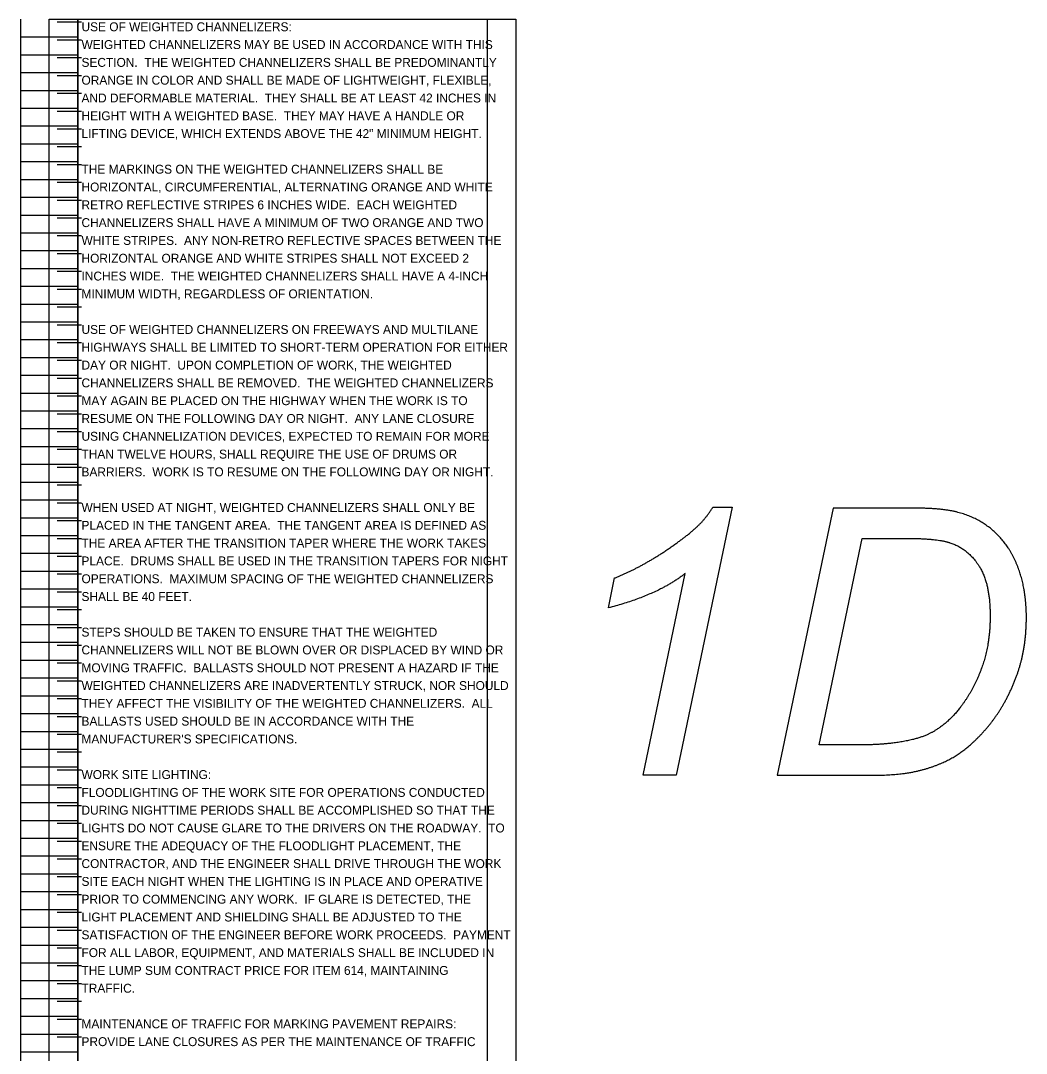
# Model space of a CAD drawing. Extents: x 12522 to 13018, y 1124 to 1902.
# Drawn here: x 12563.34 to 12579.16, y 1773.05 to 1789.29 of the extents above; entities that cross this region are included whole.
import ezdxf

# ---------------------------------------------------------------- set-up
doc = ezdxf.new("R2010")
doc.units = 0
doc.layers.add('SC_Scratch1', color=7, linetype='Continuous')
doc.layers.add('SH_Text', color=7, linetype='Continuous')

msp = doc.modelspace()

# ---------------------------------------------------------------- linework, layer by layer
at = {"layer": 'SC_Scratch1'}
for p, q in [((12563.336, 1769.151), (12563.336, 1789.311)), ((12563.336, 1769.151), (12563.336, 1789.311)), ((12564.293, 1789.261), (12563.909, 1789.261)), ((12564.236, 1769.151), (12564.236, 1789.311)), ((12564.236, 1789.311), (12564.236, 1769.151)), ((12564.236, 1769.151), (12564.236, 1789.311)), ((12563.336, 1789.031), (12564.236, 1789.031)), ((12563.336, 1789.031), (12564.236, 1789.031)), ((12564.293, 1788.981), (12563.909, 1788.981)), ((12563.336, 1788.751), (12564.236, 1788.751)), ((12563.336, 1788.751), (12564.236, 1788.751)), ((12564.293, 1788.701), (12563.909, 1788.701)), ((12563.336, 1788.471), (12564.236, 1788.471)), ((12563.336, 1788.471), (12564.236, 1788.471)), ((12564.293, 1788.421), (12563.909, 1788.421)), ((12563.336, 1788.191), (12564.236, 1788.191)), ((12563.336, 1788.191), (12564.236, 1788.191)), ((12564.293, 1788.141), (12563.909, 1788.141)), ((12563.336, 1787.911), (12564.236, 1787.911)), ((12563.336, 1787.911), (12564.236, 1787.911)), ((12564.293, 1787.861), (12563.909, 1787.861)), ((12563.336, 1787.631), (12564.236, 1787.631)), ((12563.336, 1787.631), (12564.236, 1787.631)), ((12564.293, 1787.581), (12563.909, 1787.581)), ((12563.336, 1787.351), (12564.236, 1787.351)), ((12563.336, 1787.351), (12564.236, 1787.351)), ((12564.293, 1787.301), (12563.909, 1787.301)), ((12563.336, 1787.071), (12564.236, 1787.071)), ((12563.336, 1787.071), (12564.236, 1787.071)), ((12564.293, 1787.021), (12563.909, 1787.021)), ((12563.336, 1786.791), (12564.236, 1786.791)), ((12563.336, 1786.791), (12564.236, 1786.791)), ((12564.293, 1786.741), (12563.909, 1786.741)), ((12563.336, 1786.511), (12564.236, 1786.511)), ((12563.336, 1786.511), (12564.236, 1786.511)), ((12564.293, 1786.461), (12563.909, 1786.461)), ((12563.336, 1786.231), (12564.236, 1786.231)), ((12563.336, 1786.231), (12564.236, 1786.231)), ((12564.293, 1786.181), (12563.909, 1786.181)), ((12563.336, 1785.951), (12564.236, 1785.951)), ((12563.336, 1785.951), (12564.236, 1785.951)), ((12564.293, 1785.901), (12563.909, 1785.901)), ((12563.336, 1785.671), (12564.236, 1785.671)), ((12563.336, 1785.671), (12564.236, 1785.671)), ((12564.293, 1785.621), (12563.909, 1785.621)), ((12563.336, 1785.391), (12564.236, 1785.391)), ((12563.336, 1785.391), (12564.236, 1785.391)), ((12564.293, 1785.341), (12563.909, 1785.341)), ((12563.336, 1785.111), (12564.236, 1785.111)), ((12563.336, 1785.111), (12564.236, 1785.111)), ((12564.293, 1785.061), (12563.909, 1785.061)), ((12563.336, 1784.831), (12564.236, 1784.831)), ((12563.336, 1784.831), (12564.236, 1784.831)), ((12564.293, 1784.781), (12563.909, 1784.781)), ((12563.336, 1784.551), (12564.236, 1784.551)), ((12563.336, 1784.551), (12564.236, 1784.551)), ((12564.293, 1784.501), (12563.909, 1784.501)), ((12563.336, 1784.271), (12564.236, 1784.271)), ((12563.336, 1784.271), (12564.236, 1784.271)), ((12564.293, 1784.221), (12563.909, 1784.221)), ((12563.336, 1783.991), (12564.236, 1783.991)), ((12563.336, 1783.991), (12564.236, 1783.991)), ((12564.293, 1783.941), (12563.909, 1783.941)), ((12563.336, 1783.711), (12564.236, 1783.711)), ((12563.336, 1783.711), (12564.236, 1783.711)), ((12564.293, 1783.661), (12563.909, 1783.661)), ((12563.336, 1783.431), (12564.236, 1783.431)), ((12563.336, 1783.431), (12564.236, 1783.431)), ((12564.293, 1783.381), (12563.909, 1783.381)), ((12563.336, 1783.151), (12564.236, 1783.151)), ((12563.336, 1783.151), (12564.236, 1783.151)), ((12564.293, 1783.101), (12563.909, 1783.101)), ((12563.336, 1782.871), (12564.236, 1782.871)), ((12563.336, 1782.871), (12564.236, 1782.871)), ((12564.293, 1782.821), (12563.909, 1782.821)), ((12563.336, 1782.591), (12564.236, 1782.591)), ((12563.336, 1782.591), (12564.236, 1782.591)), ((12564.293, 1782.541), (12563.909, 1782.541)), ((12563.336, 1782.311), (12564.236, 1782.311)), ((12563.336, 1782.311), (12564.236, 1782.311)), ((12564.293, 1782.261), (12563.909, 1782.261)), ((12563.336, 1782.031), (12564.236, 1782.031)), ((12563.336, 1782.031), (12564.236, 1782.031)), ((12564.293, 1781.981), (12563.909, 1781.981)), ((12563.336, 1781.751), (12564.236, 1781.751)), ((12563.336, 1781.751), (12564.236, 1781.751)), ((12564.293, 1781.701), (12563.909, 1781.701)), ((12563.336, 1781.471), (12564.236, 1781.471)), ((12563.336, 1781.471), (12564.236, 1781.471)), ((12564.293, 1781.421), (12563.909, 1781.421)), ((12563.336, 1781.191), (12564.236, 1781.191)), ((12563.336, 1781.191), (12564.236, 1781.191)), ((12564.293, 1781.141), (12563.909, 1781.141)), ((12563.336, 1780.911), (12564.236, 1780.911)), ((12563.336, 1780.911), (12564.236, 1780.911)), ((12564.293, 1780.861), (12563.909, 1780.861)), ((12563.336, 1780.631), (12564.236, 1780.631)), ((12563.336, 1780.631), (12564.236, 1780.631)), ((12564.293, 1780.581), (12563.909, 1780.581)), ((12572.582, 1780.052), (12572.68, 1780.523)), ((12572.582, 1780.052), (12572.68, 1780.523)), ((12563.336, 1780.351), (12564.236, 1780.351)), ((12563.336, 1780.351), (12564.236, 1780.351)), ((12564.293, 1780.301), (12563.909, 1780.301)), ((12563.336, 1780.071), (12564.236, 1780.071)), ((12563.336, 1780.071), (12564.236, 1780.071)), ((12564.293, 1780.021), (12563.909, 1780.021)), ((12563.336, 1779.791), (12564.236, 1779.791)), ((12563.336, 1779.791), (12564.236, 1779.791)), ((12564.293, 1779.741), (12563.909, 1779.741)), ((12563.336, 1779.511), (12564.236, 1779.511)), ((12563.336, 1779.511), (12564.236, 1779.511)), ((12564.293, 1779.461), (12563.909, 1779.461)), ((12563.336, 1779.231), (12564.236, 1779.231)), ((12563.336, 1779.231), (12564.236, 1779.231)), ((12564.293, 1779.181), (12563.909, 1779.181)), ((12563.336, 1778.951), (12564.236, 1778.951)), ((12563.336, 1778.951), (12564.236, 1778.951)), ((12564.293, 1778.901), (12563.909, 1778.901)), ((12563.336, 1778.671), (12564.236, 1778.671)), ((12563.336, 1778.671), (12564.236, 1778.671)), ((12564.293, 1778.621), (12563.909, 1778.621)), ((12563.336, 1778.391), (12564.236, 1778.391)), ((12563.336, 1778.391), (12564.236, 1778.391)), ((12564.293, 1778.341), (12563.909, 1778.341)), ((12563.336, 1778.111), (12564.236, 1778.111)), ((12563.336, 1778.111), (12564.236, 1778.111)), ((12564.293, 1778.061), (12563.909, 1778.061)), ((12563.336, 1777.831), (12564.236, 1777.831)), ((12563.336, 1777.831), (12564.236, 1777.831)), ((12564.293, 1777.781), (12563.909, 1777.781)), ((12563.336, 1777.551), (12564.236, 1777.551)), ((12563.336, 1777.551), (12564.236, 1777.551)), ((12564.293, 1777.501), (12563.909, 1777.501)), ((12563.336, 1777.271), (12564.236, 1777.271)), ((12563.336, 1777.271), (12564.236, 1777.271)), ((12564.293, 1777.221), (12563.909, 1777.221)), ((12563.336, 1776.991), (12564.236, 1776.991)), ((12563.336, 1776.991), (12564.236, 1776.991)), ((12564.293, 1776.941), (12563.909, 1776.941)), ((12563.336, 1776.711), (12564.236, 1776.711)), ((12563.336, 1776.711), (12564.236, 1776.711)), ((12564.293, 1776.661), (12563.909, 1776.661)), ((12563.336, 1776.431), (12564.236, 1776.431)), ((12563.336, 1776.431), (12564.236, 1776.431)), ((12564.293, 1776.381), (12563.909, 1776.381)), ((12563.336, 1776.151), (12564.236, 1776.151)), ((12563.336, 1776.151), (12564.236, 1776.151)), ((12564.293, 1776.101), (12563.909, 1776.101)), ((12563.336, 1775.871), (12564.236, 1775.871)), ((12563.336, 1775.871), (12564.236, 1775.871)), ((12564.293, 1775.821), (12563.909, 1775.821)), ((12563.336, 1775.591), (12564.236, 1775.591)), ((12563.336, 1775.591), (12564.236, 1775.591)), ((12564.293, 1775.541), (12563.909, 1775.541)), ((12563.336, 1775.311), (12564.236, 1775.311)), ((12563.336, 1775.311), (12564.236, 1775.311)), ((12564.293, 1775.261), (12563.909, 1775.261)), ((12563.336, 1775.031), (12564.236, 1775.031)), ((12563.336, 1775.031), (12564.236, 1775.031)), ((12564.293, 1774.981), (12563.909, 1774.981)), ((12563.336, 1774.751), (12564.236, 1774.751)), ((12563.336, 1774.751), (12564.236, 1774.751)), ((12564.293, 1774.701), (12563.909, 1774.701)), ((12563.336, 1774.471), (12564.236, 1774.471)), ((12563.336, 1774.471), (12564.236, 1774.471)), ((12564.293, 1774.421), (12563.909, 1774.421)), ((12563.336, 1774.191), (12564.236, 1774.191)), ((12563.336, 1774.191), (12564.236, 1774.191)), ((12564.293, 1774.141), (12563.909, 1774.141)), ((12563.336, 1773.911), (12564.236, 1773.911)), ((12563.336, 1773.911), (12564.236, 1773.911)), ((12564.293, 1773.861), (12563.909, 1773.861)), ((12563.336, 1773.631), (12564.236, 1773.631)), ((12563.336, 1773.631), (12564.236, 1773.631)), ((12564.293, 1773.581), (12563.909, 1773.581)), ((12563.336, 1773.351), (12564.236, 1773.351)), ((12563.336, 1773.351), (12564.236, 1773.351)), ((12564.293, 1773.301), (12563.909, 1773.301)), ((12563.336, 1773.071), (12564.236, 1773.071)), ((12563.336, 1773.071), (12564.236, 1773.071))]:
    msp.add_line(p, q, dxfattribs=at)
for points in [[(12563.786, 1789.311), (12571.126, 1789.311), (12571.126, 1769.151), (12563.786, 1769.151)], [(12564.236, 1789.311), (12570.676, 1789.311), (12570.676, 1769.151), (12564.236, 1769.151)], [(12564.236, 1789.311), (12570.676, 1789.311), (12570.676, 1769.151), (12564.236, 1769.151)]]:
    msp.add_lwpolyline(points, close=True, dxfattribs=at)
for points in [[(12574.227, 1781.637), (12574.528, 1781.637), (12573.65, 1777.421), (12573.129, 1777.421), (12573.791, 1780.594)], [(12574.227, 1781.637), (12574.528, 1781.637), (12573.65, 1777.421), (12573.129, 1777.421), (12573.791, 1780.594)], [(12577.382, 1781.621), (12576.115, 1781.621), (12575.238, 1777.421), (12576.752, 1777.421)], [(12577.382, 1781.621), (12576.115, 1781.621), (12575.238, 1777.421), (12576.752, 1777.421)], [(12576.563, 1777.898), (12575.897, 1777.898), (12576.575, 1781.144), (12577.319, 1781.144)], [(12576.563, 1777.898), (12575.897, 1777.898), (12576.575, 1781.144), (12577.319, 1781.144)]]:
    msp.add_lwpolyline(points, dxfattribs=at)
for points in [[(12574.009, 1781.36), (12574.124, 1781.474), (12574.227, 1781.637)], [(12574.009, 1781.36), (12574.124, 1781.474), (12574.227, 1781.637)], [(12578.079, 1781.555), (12577.838, 1781.621), (12577.382, 1781.621)], [(12578.079, 1781.555), (12577.838, 1781.621), (12577.382, 1781.621)], [(12578.666, 1781.238), (12578.423, 1781.466), (12578.079, 1781.555)], [(12578.666, 1781.238), (12578.423, 1781.466), (12578.079, 1781.555)], [(12573.443, 1780.926), (12573.82, 1781.174), (12574.009, 1781.36)], [(12573.443, 1780.926), (12573.82, 1781.174), (12574.009, 1781.36)], [(12579.033, 1780.67), (12578.91, 1781.011), (12578.666, 1781.238)], [(12579.033, 1780.67), (12578.91, 1781.011), (12578.666, 1781.238)], [(12577.319, 1781.144), (12577.75, 1781.144), (12577.954, 1781.078)], [(12577.319, 1781.144), (12577.75, 1781.144), (12577.954, 1781.078)], [(12577.954, 1781.078), (12578.23, 1780.989), (12578.409, 1780.716)], [(12577.954, 1781.078), (12578.23, 1780.989), (12578.409, 1780.716)], [(12572.68, 1780.523), (12573.067, 1780.677), (12573.443, 1780.926)], [(12572.68, 1780.523), (12573.067, 1780.677), (12573.443, 1780.926)], [(12573.791, 1780.594), (12573.362, 1780.256), (12572.582, 1780.052)], [(12573.791, 1780.594), (12573.362, 1780.256), (12572.582, 1780.052)], [(12578.409, 1780.716), (12578.587, 1780.442), (12578.587, 1779.932)], [(12578.409, 1780.716), (12578.587, 1780.442), (12578.587, 1779.932)], [(12579.157, 1779.905), (12579.157, 1780.329), (12579.033, 1780.67)], [(12579.157, 1779.905), (12579.157, 1780.329), (12579.033, 1780.67)], [(12578.587, 1779.932), (12578.587, 1779.474), (12578.456, 1779.114)], [(12578.587, 1779.932), (12578.587, 1779.474), (12578.456, 1779.114)], [(12579.003, 1778.981), (12579.157, 1779.398), (12579.157, 1779.905)], [(12579.003, 1778.981), (12579.157, 1779.398), (12579.157, 1779.905)], [(12578.456, 1779.114), (12578.326, 1778.755), (12578.107, 1778.474)], [(12578.456, 1779.114), (12578.326, 1778.755), (12578.107, 1778.474)], [(12578.602, 1778.247), (12578.85, 1778.564), (12579.003, 1778.981)], [(12578.602, 1778.247), (12578.85, 1778.564), (12579.003, 1778.981)], [(12578.107, 1778.474), (12577.941, 1778.262), (12577.737, 1778.133)], [(12578.107, 1778.474), (12577.941, 1778.262), (12577.737, 1778.133)], [(12577.737, 1778.133), (12577.582, 1778.033), (12577.364, 1777.981)], [(12577.737, 1778.133), (12577.582, 1778.033), (12577.364, 1777.981)], [(12578.083, 1777.752), (12578.354, 1777.931), (12578.602, 1778.247)], [(12578.083, 1777.752), (12578.354, 1777.931), (12578.602, 1778.247)], [(12577.364, 1777.981), (12577.014, 1777.898), (12576.563, 1777.898)], [(12577.364, 1777.981), (12577.014, 1777.898), (12576.563, 1777.898)], [(12577.443, 1777.487), (12577.812, 1777.573), (12578.083, 1777.752)], [(12577.443, 1777.487), (12577.812, 1777.573), (12578.083, 1777.752)], [(12576.752, 1777.421), (12577.162, 1777.421), (12577.443, 1777.487)], [(12576.752, 1777.421), (12577.162, 1777.421), (12577.443, 1777.487)]]:
    msp.add_open_spline(points, degree=2, dxfattribs=at)

# ---------------------------------------------------------------- texts
at = {"layer": 'SH_Text'}
for s, p in [('USE OF WEIGHTED CHANNELIZERS:', (12564.293, 1789.121)), ('WEIGHTED CHANNELIZERS MAY BE USED IN ACCORDANCE WITH THIS ', (12564.293, 1788.841)), ('SECTION.  THE WEIGHTED CHANNELIZERS SHALL BE PREDOMINANTLY ', (12564.293, 1788.561)), ('ORANGE IN COLOR AND SHALL BE MADE OF LIGHTWEIGHT, FLEXIBLE, ', (12564.293, 1788.281)), ('AND DEFORMABLE MATERIAL.  THEY SHALL BE AT LEAST 42 INCHES IN ', (12564.293, 1788.001)), ('HEIGHT WITH A WEIGHTED BASE.  THEY MAY HAVE A HANDLE OR ', (12564.293, 1787.721)), ('LIFTING DEVICE, WHICH EXTENDS ABOVE THE 42" MINIMUM HEIGHT.', (12564.293, 1787.441)), ('THE MARKINGS ON THE WEIGHTED CHANNELIZERS SHALL BE ', (12564.293, 1786.881)), ('HORIZONTAL, CIRCUMFERENTIAL, ALTERNATING ORANGE AND WHITE ', (12564.293, 1786.601)), ('RETRO REFLECTIVE STRIPES 6 INCHES WIDE.  EACH WEIGHTED ', (12564.293, 1786.321)), ('CHANNELIZERS SHALL HAVE A MINIMUM OF TWO ORANGE AND TWO ', (12564.293, 1786.041)), ('WHITE STRIPES.  ANY NON-RETRO REFLECTIVE SPACES BETWEEN THE ', (12564.293, 1785.761)), ('HORIZONTAL ORANGE AND WHITE STRIPES SHALL NOT EXCEED 2 ', (12564.293, 1785.481)), ('INCHES WIDE.  THE WEIGHTED CHANNELIZERS SHALL HAVE A 4-INCH ', (12564.293, 1785.201)), ('MINIMUM WIDTH, REGARDLESS OF ORIENTATION.', (12564.293, 1784.921)), ('USE OF WEIGHTED CHANNELIZERS ON FREEWAYS AND MULTILANE ', (12564.293, 1784.361)), ('HIGHWAYS SHALL BE LIMITED TO SHORT-TERM OPERATION FOR EITHER ', (12564.293, 1784.081)), ('DAY OR NIGHT.  UPON COMPLETION OF WORK, THE WEIGHTED ', (12564.293, 1783.801)), ('CHANNELIZERS SHALL BE REMOVED.  THE WEIGHTED CHANNELIZERS ', (12564.293, 1783.521)), ('MAY AGAIN BE PLACED ON THE HIGHWAY WHEN THE WORK IS TO ', (12564.293, 1783.241)), ('RESUME ON THE FOLLOWING DAY OR NIGHT.  ANY LANE CLOSURE ', (12564.293, 1782.961)), ('USING CHANNELIZATION DEVICES, EXPECTED TO REMAIN FOR MORE ', (12564.293, 1782.681)), ('THAN TWELVE HOURS, SHALL REQUIRE THE USE OF DRUMS OR ', (12564.293, 1782.401)), ('BARRIERS.  WORK IS TO RESUME ON THE FOLLOWING DAY OR NIGHT.', (12564.293, 1782.121)), ('WHEN USED AT NIGHT, WEIGHTED CHANNELIZERS SHALL ONLY BE ', (12564.293, 1781.561)), ('PLACED IN THE TANGENT AREA.  THE TANGENT AREA IS DEFINED AS ', (12564.293, 1781.281)), ('THE AREA AFTER THE TRANSITION TAPER WHERE THE WORK TAKES ', (12564.293, 1781.001)), ('PLACE.  DRUMS SHALL BE USED IN THE TRANSITION TAPERS FOR NIGHT ', (12564.293, 1780.721)), ('OPERATIONS.  MAXIMUM SPACING OF THE WEIGHTED CHANNELIZERS ', (12564.293, 1780.441)), ('SHALL BE 40 FEET.', (12564.293, 1780.161)), ('STEPS SHOULD BE TAKEN TO ENSURE THAT THE WEIGHTED ', (12564.293, 1779.601)), ('CHANNELIZERS WILL NOT BE BLOWN OVER OR DISPLACED BY WIND OR ', (12564.293, 1779.321)), ('MOVING TRAFFIC.  BALLASTS SHOULD NOT PRESENT A HAZARD IF THE ', (12564.293, 1779.041)), ('WEIGHTED CHANNELIZERS ARE INADVERTENTLY STRUCK, NOR SHOULD ', (12564.293, 1778.761)), ('THEY AFFECT THE VISIBILITY OF THE WEIGHTED CHANNELIZERS.  ALL ', (12564.293, 1778.481)), ('BALLASTS USED SHOULD BE IN ACCORDANCE WITH THE ', (12564.293, 1778.201)), ("MANUFACTURER'S SPECIFICATIONS.", (12564.293, 1777.921)), ('WORK SITE LIGHTING:', (12564.293, 1777.361)), ('FLOODLIGHTING OF THE WORK SITE FOR OPERATIONS CONDUCTED ', (12564.293, 1777.081)), ('DURING NIGHTTIME PERIODS SHALL BE ACCOMPLISHED SO THAT THE ', (12564.293, 1776.801)), ('LIGHTS DO NOT CAUSE GLARE TO THE DRIVERS ON THE ROADWAY.  TO ', (12564.293, 1776.521)), ('ENSURE THE ADEQUACY OF THE FLOODLIGHT PLACEMENT, THE ', (12564.293, 1776.241)), ('CONTRACTOR, AND THE ENGINEER SHALL DRIVE THROUGH THE WORK ', (12564.293, 1775.961)), ('SITE EACH NIGHT WHEN THE LIGHTING IS IN PLACE AND OPERATIVE ', (12564.293, 1775.681)), ('PRIOR TO COMMENCING ANY WORK.  IF GLARE IS DETECTED, THE ', (12564.293, 1775.401)), ('LIGHT PLACEMENT AND SHIELDING SHALL BE ADJUSTED TO THE ', (12564.293, 1775.121)), ('SATISFACTION OF THE ENGINEER BEFORE WORK PROCEEDS.  PAYMENT ', (12564.293, 1774.841)), ('FOR ALL LABOR, EQUIPMENT, AND MATERIALS SHALL BE INCLUDED IN ', (12564.293, 1774.561)), ('THE LUMP SUM CONTRACT PRICE FOR ITEM 614, MAINTAINING ', (12564.293, 1774.281)), ('TRAFFIC.', (12564.293, 1774.001)), ('MAINTENANCE OF TRAFFIC FOR MARKING PAVEMENT REPAIRS:', (12564.293, 1773.441)), ('PROVIDE LANE CLOSURES AS PER THE MAINTENANCE OF TRAFFIC ', (12564.293, 1773.161))]:
    msp.add_text(s, height=0.14, dxfattribs=at).set_placement(p)

doc.saveas('drawing.dxf')
